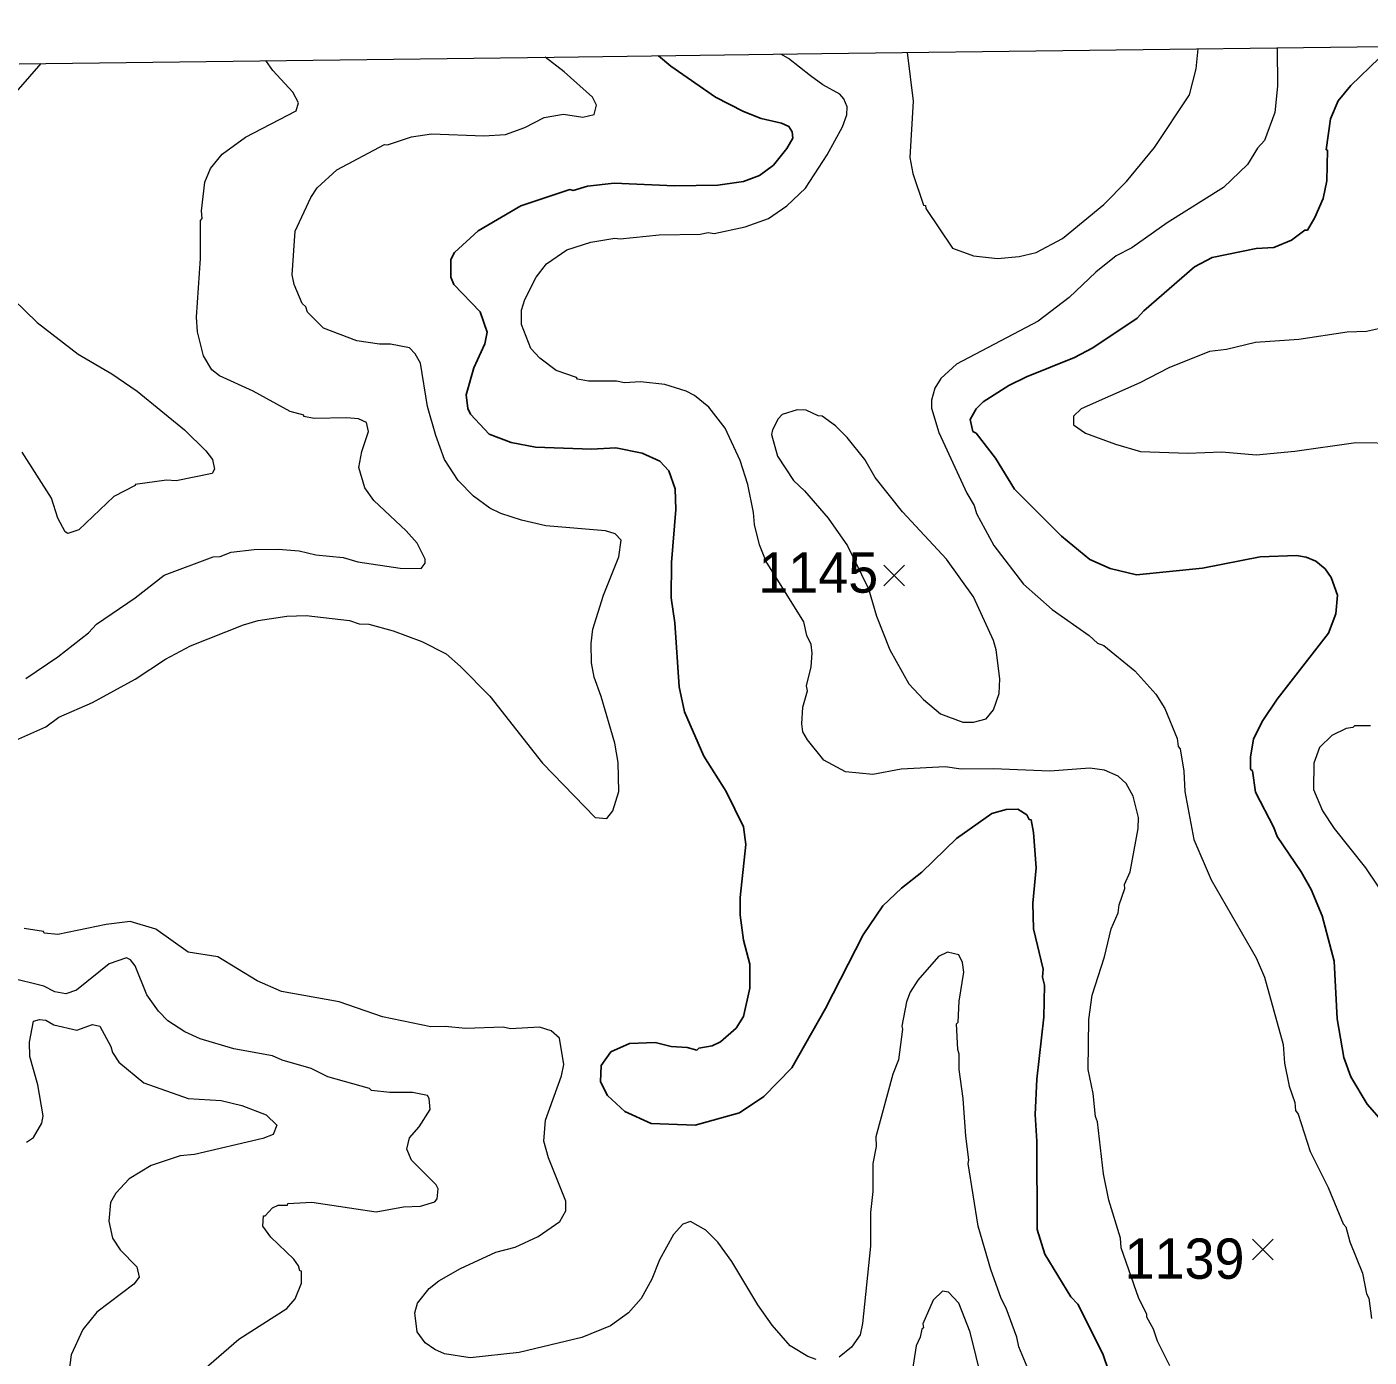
# Model space of a CAD drawing. Extents: x 265.7 to 292.1, y 7676.2 to 7704.2.
# Drawn here: x 285.928 to 288.593, y 7701.561 to 7704.203 of the extents above; entities that cross this region are included whole.
import ezdxf
from ezdxf.enums import TextEntityAlignment as Align

# ---------------------------------------------------------------- set-up
doc = ezdxf.new("R2010")
doc.units = 0
doc.header["$LTSCALE"] = 0.032
for name, color, linetype, lineweight in [('1', 7, 'Continuous', 25), ('2', 7, 'Continuous', 13), ('21', 7, 'Continuous', 25), ('63', 7, 'Continuous', 25)]:
    doc.layers.add(name, color=color, linetype=linetype, lineweight=lineweight)
doc.layers.add('61', color=7, linetype='Continuous')

msp = doc.modelspace()

# ---------------------------------------------------------------- linework, layer by layer
at = {"layer": '1'}
for points in [[(287.2886, 7702.1794), (287.3053, 7702.1874), (287.3364, 7702.2146), (287.3508, 7702.2377), (287.3636, 7702.2936), (287.3636, 7702.3414), (287.3508, 7702.3893), (287.3444, 7702.4388), (287.3444, 7702.4739), (287.3556, 7702.5792), (287.3508, 7702.6144), (287.3165, 7702.6846), (287.2718, 7702.7548), (287.2335, 7702.8426), (287.2231, 7702.892), (287.2144, 7703.0197), (287.2072, 7703.0692), (287.208, 7703.1394), (287.2167, 7703.2447), (287.2152, 7703.2854), (287.2024, 7703.3213), (287.1848, 7703.3405), (287.1497, 7703.3564), (287.0971, 7703.3668), (287.0492, 7703.3644), (286.9375, 7703.3684), (286.8896, 7703.3772), (286.8457, 7703.3939), (286.809, 7703.4339), (286.8034, 7703.445), (286.8002, 7703.4722), (286.8154, 7703.5256), (286.8369, 7703.5735), (286.8417, 7703.5966), (286.8281, 7703.6373), (286.7755, 7703.6916), (286.7699, 7703.706), (286.7699, 7703.7411), (286.7771, 7703.7546), (286.8242, 7703.7977), (286.9087, 7703.8472), (287.0061, 7703.8799), (287.0125, 7703.8783), (287.0412, 7703.8863), (287.0939, 7703.8927), (287.2136, 7703.8871), (287.2997, 7703.8887), (287.3508, 7703.8959), (287.3827, 7703.9078), (287.4107, 7703.9286), (287.437, 7703.9613), (287.449, 7703.9821), (287.4474, 7703.9948), (287.441, 7704.0052), (287.4266, 7704.0116), (287.3859, 7704.0211), (287.3508, 7704.0347), (287.295, 7704.0634), (287.2064, 7704.1249), (287.1821, 7704.1457)], [(288.6129, 7704.1406), (288.5565, 7704.0866), (288.5318, 7704.0562), (288.5166, 7704.0204), (288.5078, 7703.9589), (288.5102, 7703.9581), (288.5094, 7703.8975), (288.5015, 7703.8624), (288.4855, 7703.8241), (288.4704, 7703.7993), (288.4656, 7703.7993), (288.4392, 7703.7794), (288.4041, 7703.765), (288.369, 7703.7626), (288.2812, 7703.745), (288.2461, 7703.7267), (288.1456, 7703.6389), (288.1328, 7703.6246), (288.0442, 7703.5655), (288.0083, 7703.5464), (287.9126, 7703.5081), (287.8775, 7703.4905), (287.8264, 7703.4586), (287.8128, 7703.4442), (287.8009, 7703.4235), (287.8064, 7703.3995), (287.8128, 7703.3963), (287.8511, 7703.3461), (287.8886, 7703.2846), (287.982, 7703.1913), (288.0387, 7703.145), (288.0786, 7703.1274), (288.1312, 7703.1147), (288.2621, 7703.1282), (288.377, 7703.1506), (288.4488, 7703.153), (288.468, 7703.1498), (288.4871, 7703.1418), (288.5055, 7703.1266), (288.5174, 7703.1091), (288.5302, 7703.074), (288.527, 7703.0373), (288.5126, 7702.999), (288.4105, 7702.8681), (288.381, 7702.8234), (288.3634, 7702.7883), (288.3578, 7702.7532), (288.3578, 7702.7285), (288.3618, 7702.7253), (288.3674, 7702.683), (288.4041, 7702.6128), (288.4105, 7702.5952), (288.4584, 7702.525), (288.4783, 7702.4899), (288.4999, 7702.4372), (288.5238, 7702.3478), (288.5294, 7702.2329), (288.543, 7702.1563), (288.5565, 7702.118), (288.5892, 7702.0638), (288.6882, 7701.9504)], [(288.0761, 7701.5323), (288.0642, 7701.5674), (288.0147, 7701.6664), (288.0011, 7701.6807), (287.9493, 7701.7653), (287.9341, 7701.8148), (287.9333, 7701.9903), (287.9301, 7702.043), (287.9333, 7702.1132), (287.9469, 7702.2361), (287.9485, 7702.3), (287.9445, 7702.3159), (287.9461, 7702.3319), (287.9269, 7702.4117), (287.9253, 7702.4627), (287.9317, 7702.533), (287.9269, 7702.6032), (287.9221, 7702.6279), (287.9182, 7702.6287), (287.9134, 7702.6383), (287.8958, 7702.6494), (287.8727, 7702.6486), (287.8439, 7702.6407), (287.7737, 7702.5912), (287.7051, 7702.5242), (287.6644, 7702.4922), (287.6277, 7702.4571), (287.5886, 7702.3997), (287.5136, 7702.2537), (287.4466, 7702.1356), (287.3915, 7702.0789), (287.3428, 7702.0462), (287.2551, 7702.0215), (287.1673, 7702.0254), (287.1154, 7702.0486), (287.0811, 7702.0805), (287.0667, 7702.1076), (287.0683, 7702.1404), (287.0875, 7702.1675), (287.1242, 7702.1842)], [(287.1242, 7702.1842), (287.1753, 7702.1858), (287.2072, 7702.1779), (287.2391, 7702.1763), (287.2583, 7702.1707), (287.2622, 7702.1747), (287.2886, 7702.1794)]]:
    msp.add_lwpolyline(points, dxfattribs=at)
at = {"layer": '2'}
for points in [[(287.6761, 7704.152), (287.6875, 7704.0555), (287.6812, 7703.9438), (287.6868, 7703.9118), (287.7083, 7703.8488), (287.7123, 7703.848), (287.7131, 7703.8424), (287.7658, 7703.7634), (287.8073, 7703.7482), (287.8551, 7703.7427), (287.8982, 7703.7467), (287.9317, 7703.7546), (287.9844, 7703.7826), (288.0666, 7703.8504), (288.1113, 7703.8959), (288.1671, 7703.9637), (288.2365, 7704.0682), (288.2499, 7704.1199), (288.2537, 7704.1593)], [(288.4102, 7704.1612), (288.4109, 7704.0851), (288.4057, 7704.0331), (288.385, 7703.9773), (288.3714, 7703.9621), (288.3515, 7703.9294), (288.3036, 7703.8839), (288.1919, 7703.8137), (288.1216, 7703.7642), (288.0905, 7703.7482), (288.0506, 7703.7155), (287.9972, 7703.6653), (287.9357, 7703.6182), (287.7737, 7703.5328), (287.7426, 7703.5049), (287.7306, 7703.4857), (287.7243, 7703.4618), (287.7243, 7703.4458), (287.7386, 7703.3971), (287.7945, 7703.2767), (287.8088, 7703.2527), (287.8136, 7703.2368), (287.8479, 7703.1729), (287.907, 7703.0963), (287.9636, 7703.046), (288.0371, 7702.9942), (288.0538, 7702.979), (288.0666, 7702.9742), (288.128, 7702.924), (288.1695, 7702.8777), (288.1871, 7702.849), (288.2118, 7702.7899), (288.2142, 7702.7739), (288.2182, 7702.7692), (288.2254, 7702.7245), (288.227, 7702.6846), (288.2453, 7702.5888), (288.2796, 7702.509), (288.369, 7702.3542), (288.385, 7702.3159), (288.4225, 7702.1819), (288.4249, 7702.1452), (288.4344, 7702.0989), (288.4456, 7702.0669), (288.4472, 7702.051), (288.452, 7702.0438), (288.4759, 7701.9696), (288.5118, 7701.8978), (288.5414, 7701.826), (288.547, 7701.8196), (288.5549, 7701.7901), (288.5797, 7701.7278), (288.5876, 7701.6871), (288.5924, 7701.6783), (288.598, 7701.6376)], [(286.7108, 7703.1274), (286.7188, 7703.1378), (286.7188, 7703.1458), (286.7029, 7703.1777), (286.6813, 7703.2024), (286.6167, 7703.2623), (286.5991, 7703.2878), (286.5872, 7703.3277), (286.5927, 7703.3596), (286.6063, 7703.3995), (286.6023, 7703.4171), (286.5864, 7703.4243), (286.5624, 7703.4267), (286.4986, 7703.4251), (286.4778, 7703.4291), (286.4778, 7703.4315), (286.4507, 7703.4394), (286.3773, 7703.4793), (286.3103, 7703.5097), (286.2951, 7703.5216), (286.2783, 7703.5496), (286.2664, 7703.5974), (286.2648, 7703.6262), (286.2728, 7703.7427), (286.2728, 7703.8185), (286.276, 7703.8225), (286.2744, 7703.8376), (286.2815, 7703.8943), (286.2927, 7703.9214), (286.3158, 7703.9501), (286.3621, 7703.9836), (286.4627, 7704.0363), (286.4675, 7704.0523), (286.4563, 7704.073), (286.4161, 7704.1166), (286.4026, 7704.1359)], [(287.0588, 7704.0475), (287.0508, 7704.0634), (286.9949, 7704.1137), (286.9571, 7704.1429)], [(287.1832, 7703.7897), (287.2646, 7703.7913), (287.2806, 7703.7945), (287.2926, 7703.7929), (287.354, 7703.8057), (287.4003, 7703.8225), (287.437, 7703.8472), (287.4737, 7703.8823), (287.5168, 7703.9485), (287.5471, 7704.0044), (287.5559, 7704.0283), (287.5567, 7704.0443), (287.5503, 7704.0603), (287.5423, 7704.069), (287.5084, 7704.0876), (287.4836, 7704.1058), (287.44, 7704.1399), (287.4248, 7704.1488)], [(285.9554, 7704.1302), (285.8834, 7704.0475)], [(285.8762, 7702.7731), (285.9656, 7702.813), (285.9911, 7702.8322), (286.0581, 7702.8609), (286.1427, 7702.9072), (286.2033, 7702.9471), (286.2528, 7702.9734), (286.3582, 7703.0157), (286.3869, 7703.0237), (286.4443, 7703.0325), (286.4826, 7703.0341), (286.5688, 7703.0237), (286.588, 7703.0173), (286.6071, 7703.0165), (286.655, 7703.0037), (286.7124, 7702.9822), (286.7603, 7702.9575), (286.7891, 7702.9327), (286.8473, 7702.8737), (286.9518, 7702.7404), (287.0564, 7702.6327), (287.0795, 7702.6311), (287.0915, 7702.6463), (287.1034, 7702.6846), (287.1018, 7702.742), (287.0955, 7702.7803), (287.0683, 7702.8729), (287.054, 7702.9112), (287.0492, 7702.9399), (287.0484, 7702.9782), (287.0516, 7703.0069), (287.0731, 7703.074), (287.1034, 7703.1506), (287.1082, 7703.1833), (287.0963, 7703.1961), (287.0771, 7703.2024), (286.9582, 7703.212), (286.9103, 7703.2232), (286.8688, 7703.2368), (286.8473, 7703.2471), (286.8146, 7703.2711), (286.7843, 7703.3022), (286.7571, 7703.3437), (286.7396, 7703.3916), (286.7236, 7703.449), (286.7092, 7703.5352), (286.6989, 7703.5536), (286.6877, 7703.5655), (286.6502, 7703.5727), (286.6279, 7703.5727), (286.5832, 7703.5791), (286.5169, 7703.6046), (286.485, 7703.6365), (286.4818, 7703.6469), (286.4746, 7703.6533), (286.4587, 7703.6916), (286.4547, 7703.7108), (286.4603, 7703.7969), (286.4914, 7703.864), (286.5042, 7703.8831), (286.5433, 7703.919), (286.6382, 7703.9693), (286.6438, 7703.9685), (286.6917, 7703.9844), (286.7316, 7703.9908), (286.8353, 7703.9868), (286.8784, 7703.9892), (286.9167, 7704.0028), (286.955, 7704.0227), (286.9933, 7704.0299), (287.0316, 7704.0235), (287.054, 7704.0291), (287.0588, 7704.0475)], [(286.9391, 7703.706), (286.9598, 7703.7323), (286.9997, 7703.7602), (287.0476, 7703.7754), (287.0955, 7703.7834), (287.1058, 7703.7818), (287.1832, 7703.7897)], [(288.1974, 7701.5435), (288.1727, 7701.593), (288.1647, 7701.6169), (288.152, 7701.6408), (288.152, 7701.6464), (288.136, 7701.6775), (288.1009, 7701.7781), (288.0993, 7701.7972), (288.0762, 7701.873), (288.0658, 7701.9249), (288.0538, 7702.0286), (288.0498, 7702.039), (288.045, 7702.0845), (288.0355, 7702.1324), (288.0363, 7702.2313), (288.0434, 7702.28), (288.0674, 7702.3558), (288.0809, 7702.4117), (288.0945, 7702.4436), (288.0969, 7702.4595), (288.1081, 7702.4915), (288.1073, 7702.4994), (288.1184, 7702.525), (288.1344, 7702.6112), (288.1352, 7702.6327), (288.1248, 7702.675), (288.1105, 7702.7005), (288.0945, 7702.7149), (288.0674, 7702.7269), (288.0387, 7702.7308), (287.9589, 7702.7245), (287.8471, 7702.7292), (287.7833, 7702.7285), (287.7514, 7702.7332), (287.6636, 7702.7285), (287.6078, 7702.7181), (287.5535, 7702.7237), (287.5104, 7702.7468), (287.4777, 7702.7867), (287.4689, 7702.8027), (287.4665, 7702.8186), (287.4689, 7702.8521), (287.4777, 7702.8841), (287.4761, 7702.8944), (287.4849, 7702.9319), (287.4873, 7702.9591), (287.4849, 7702.9766), (287.4769, 7702.9942), (287.4705, 7703.0213), (287.3961, 7703.1413), (287.3827, 7703.1745), (287.3724, 7703.2144), (287.3708, 7703.2384), (287.3596, 7703.2942), (287.3444, 7703.3421), (287.3141, 7703.4059), (287.2822, 7703.4474), (287.2535, 7703.4706), (287.2367, 7703.4793), (287.1944, 7703.4929), (287.1465, 7703.4977), (287.1146, 7703.4961), (287.0987, 7703.4993), (287.0428, 7703.4993), (287.0213, 7703.5033), (287.0189, 7703.5065), (286.979, 7703.5208), (286.9462, 7703.5448), (286.9287, 7703.5639), (286.9103, 7703.6118), (286.9103, 7703.6405), (286.9167, 7703.6613), (286.9391, 7703.706)], [(285.877, 7703.6852), (285.948, 7703.6158), (286.0294, 7703.5527), (286.0964, 7703.5136), (286.1467, 7703.4793), (286.2408, 7703.4027), (286.2831, 7703.3612), (286.2967, 7703.3437), (286.3007, 7703.3245), (286.2959, 7703.3158), (286.2241, 7703.3014), (286.2049, 7703.303), (286.1427, 7703.2942), (286.1427, 7703.2918), (286.1004, 7703.2703), (286.031, 7703.204), (286.0094, 7703.1969), (286.0039, 7703.2), (285.9895, 7703.2272), (285.9767, 7703.2671), (285.9185, 7703.3581)], [(288.6355, 7703.6086), (288.5877, 7703.5982), (288.5494, 7703.5966), (288.4536, 7703.5823), (288.3674, 7703.5759), (288.31, 7703.5623), (288.2764, 7703.5583), (288.1951, 7703.5256), (288.1376, 7703.4961), (288.0211, 7703.4442), (288.0059, 7703.4299), (288.0059, 7703.4123), (288.0299, 7703.3963), (288.0897, 7703.374), (288.1392, 7703.3596), (288.2334, 7703.3564), (288.3004, 7703.3588), (288.369, 7703.3533), (288.4456, 7703.3604), (288.5669, 7703.3772), (288.6507, 7703.3764)], [(285.9257, 7702.9088), (285.9895, 7702.9519), (286.0501, 7702.9998), (286.0661, 7703.0165), (286.1427, 7703.0692), (286.2002, 7703.1139), (286.2975, 7703.1506), (286.3119, 7703.1514), (286.3334, 7703.1594), (286.3789, 7703.1649), (286.4268, 7703.1657)], [(286.4268, 7703.1657), (286.4683, 7703.1625), (286.5018, 7703.1546), (286.556, 7703.149), (286.5848, 7703.1402), (286.6694, 7703.1282), (286.7108, 7703.1274)], [(288.5956, 7702.8146), (288.5637, 7702.8146), (288.5605, 7702.8114), (288.5478, 7702.8098), (288.519, 7702.7955), (288.4943, 7702.7715), (288.4831, 7702.7404), (288.4823, 7702.6886), (288.5007, 7702.6463), (288.5238, 7702.6112), (288.5861, 7702.533), (288.6363, 7702.4579)], [(286.3071, 7702.3558), (286.248, 7702.3654), (286.1842, 7702.4109), (286.1331, 7702.426), (286.0852, 7702.4204), (285.9895, 7702.4005), (285.9624, 7702.4029), (285.9608, 7702.4061), (285.9225, 7702.4125)], [(286.1339, 7702.3502), (286.1259, 7702.3542), (286.0916, 7702.3422), (286.0262, 7702.2896), (286.0055, 7702.2824), (285.9831, 7702.2864), (285.9616, 7702.2976)], [(286.2496, 7701.5108), (286.3486, 7701.5969), (286.4443, 7701.6576), (286.4603, 7701.6767), (286.4731, 7701.7079), (286.4731, 7701.7318), (286.4699, 7701.7326), (286.4675, 7701.7422), (286.4579, 7701.7557), (286.4124, 7701.7996), (286.3964, 7701.8212), (286.398, 7701.8419), (286.4012, 7701.8419), (286.4156, 7701.8579), (286.4268, 7701.8627), (286.4451, 7701.8627), (286.4459, 7701.8659), (286.4938, 7701.869), (286.6215, 7701.8499), (286.6757, 7701.8595), (286.7093, 7701.8611), (286.738, 7701.8698), (286.7428, 7701.8754), (286.7444, 7701.8954), (286.7404, 7701.9034), (286.6917, 7701.952), (286.6821, 7701.9744), (286.6877, 7701.9967), (286.7069, 7702.0183), (286.7284, 7702.0526), (286.7268, 7702.0749), (286.7236, 7702.0805), (286.6933, 7702.0869), (286.6486, 7702.0869), (286.6119, 7702.0909), (286.6079, 7702.0949), (286.5257, 7702.118), (286.4922, 7702.134), (286.4348, 7702.1507), (286.4156, 7702.1595), (286.339, 7702.1731), (286.272, 7702.193), (286.2416, 7702.2074), (286.2081, 7702.2289), (286.189, 7702.2481), (286.1658, 7702.2808), (286.1427, 7702.3383), (286.1339, 7702.3502)], [(286.7587, 7702.2178), (286.73, 7702.217), (286.6342, 7702.2369), (286.5481, 7702.2664), (286.4332, 7702.2872), (286.3853, 7702.3087), (286.3071, 7702.3558)], [(287.9174, 7701.5339), (287.8974, 7701.5818), (287.8934, 7701.6009), (287.8727, 7701.6584), (287.8623, 7701.6775), (287.8416, 7701.735), (287.8168, 7701.8212), (287.7969, 7701.9457), (287.7985, 7701.9528), (287.7921, 7701.9999), (287.7873, 7702.0749), (287.7793, 7702.1324), (287.7793, 7702.1627), (287.7761, 7702.1723), (287.7737, 7702.2233), (287.7769, 7702.2265), (287.7793, 7702.268), (287.7881, 7702.3255), (287.7857, 7702.3446), (287.7785, 7702.3598), (287.7562, 7702.3654), (287.7378, 7702.3566), (287.6971, 7702.3095), (287.682, 7702.2856), (287.6748, 7702.2664), (287.6652, 7702.2186), (287.6668, 7702.2122), (287.6588, 7702.1515), (287.6476, 7702.1228), (287.6133, 7701.9983), (287.6141, 7701.9792), (287.6078, 7701.9457), (287.6078, 7701.8898), (287.603, 7701.8483), (287.603, 7701.7813), (287.587, 7701.6281), (287.5822, 7701.6057), (287.5655, 7701.581), (287.5407, 7701.561)], [(285.9616, 7702.2976), (285.8921, 7702.3151)], [(285.9273, 7701.9879), (285.9408, 7701.9975), (285.9576, 7702.0255), (285.96, 7702.0406), (285.9496, 7702.1021), (285.9336, 7702.1579), (285.9328, 7702.1866), (285.9408, 7702.2281), (285.9528, 7702.2313), (285.9656, 7702.2305), (285.9815, 7702.2209), (286.027, 7702.2106), (286.0581, 7702.2217), (286.0725, 7702.2186), (286.0948, 7702.1779), (286.098, 7702.1659), (286.1108, 7702.1467), (286.1602, 7702.106), (286.248, 7702.0749), (286.3135, 7702.0709), (286.355, 7702.0606), (286.4028, 7702.0422), (286.4244, 7702.0215), (286.4172, 7702.0031), (286.3965, 7701.9951), (286.2608, 7701.9632), (286.2321, 7701.9608), (286.1746, 7701.9417), (286.1307, 7701.9153), (286.1044, 7701.8866), (286.094, 7701.8683), (286.0908, 7701.8308), (286.098, 7701.7972), (286.1132, 7701.7741), (286.1459, 7701.7406), (286.1507, 7701.7198), (286.1403, 7701.7063), (286.0669, 7701.6504), (286.039, 7701.6161), (286.0158, 7701.5658), (286.007, 7701.5004)], [(287.4952, 7701.5562), (287.4785, 7701.5626), (287.4434, 7701.5834), (287.4075, 7701.6249), (287.3795, 7701.6648), (287.3277, 7701.751), (287.2997, 7701.7893), (287.2758, 7701.8132), (287.2455, 7701.8307), (287.2303, 7701.8252), (287.212, 7701.8044), (287.184, 7701.7541), (287.1689, 7701.7158), (287.1473, 7701.6775), (287.1226, 7701.6488), (287.0867, 7701.6233), (287.03, 7701.6001), (286.9056, 7701.5706), (286.8082, 7701.5594), (286.7571, 7701.5674), (286.738, 7701.5762), (286.7188, 7701.5898), (286.7029, 7701.6113), (286.6981, 7701.6488), (286.7037, 7701.668), (286.7268, 7701.6975), (286.746, 7701.7126), (286.7891, 7701.7374), (286.8593, 7701.7693), (286.8976, 7701.7797), (286.9431, 7701.8004), (286.9861, 7701.8307), (286.9981, 7701.8515), (286.9981, 7701.8707), (286.9638, 7701.9568), (286.9542, 7701.9903), (286.9574, 7702.0318), (286.9893, 7702.1196), (286.9941, 7702.142), (286.9853, 7702.1946), (286.9686, 7702.209), (286.9455, 7702.2162), (286.888, 7702.213), (286.8736, 7702.2162), (286.7986, 7702.2138), (286.7587, 7702.2178)], [(287.8248, 7701.514), (287.8009, 7701.6105), (287.7785, 7701.668), (287.7578, 7701.6903), (287.7458, 7701.6919), (287.7274, 7701.6743), (287.7067, 7701.6273), (287.7083, 7701.6193), (287.7051, 7701.6169), (287.7019, 7701.6009), (287.6939, 7701.5834), (287.6796, 7701.494)]]:
    msp.add_lwpolyline(points, dxfattribs=at)
msp.add_lwpolyline([(287.5574, 7703.1722), (287.5987, 7703.0872), (287.6149, 7703.0325), (287.6413, 7702.9655), (287.6788, 7702.8984), (287.7083, 7702.8673), (287.7418, 7702.8386), (287.7865, 7702.8218), (287.8073, 7702.8218), (287.8328, 7702.829), (287.8471, 7702.8466), (287.8583, 7702.8793), (287.8599, 7702.908), (287.8527, 7702.9655), (287.8471, 7702.9846), (287.8072, 7703.0708), (287.7538, 7703.1458), (287.6668, 7703.24), (287.6125, 7703.3078), (287.5918, 7703.3437), (287.5567, 7703.3876), (287.5335, 7703.4107), (287.5072, 7703.4299), (287.4992, 7703.4307), (287.4753, 7703.4418), (287.4577, 7703.4426), (287.4274, 7703.4331), (287.4194, 7703.4243), (287.4083, 7703.4027), (287.4067, 7703.3932), (287.4186, 7703.3501), (287.4498, 7703.3022), (287.4721, 7703.2814), (287.5192, 7703.2272)], close=True, dxfattribs=at)
at = {"layer": '21'}
for p, q in [((287.6293, 7703.1339), (287.6705, 7703.0927)), ((287.6705, 7703.1339), (287.6293, 7703.0927)), ((288.3616, 7701.7957), (288.4028, 7701.7545)), ((288.4028, 7701.7957), (288.3616, 7701.7545))]:
    msp.add_line(p, q, dxfattribs=at)
at = {"layer": '63', "lineweight": 13}
msp.add_lwpolyline([(285.9123, 7704.1296), (286.4437, 7704.1364), (286.9751, 7704.1431), (287.5065, 7704.1498), (288.0379, 7704.1565), (288.5693, 7704.1632), (289.1007, 7704.1699), (289.6321, 7704.1765), (290.1635, 7704.1832), (290.6949, 7704.1898), (291.2263, 7704.1964), (291.7577, 7704.203)], dxfattribs=at)

# ---------------------------------------------------------------- texts
at = {"layer": '61'}
for s, p in [('1145', (287.4993, 7703.0792)), ('1139', (288.2265, 7701.7167))]:
    msp.add_text(s, height=0.08, dxfattribs=at).set_placement(p, align=Align.CENTER)

doc.saveas('drawing.dxf')
